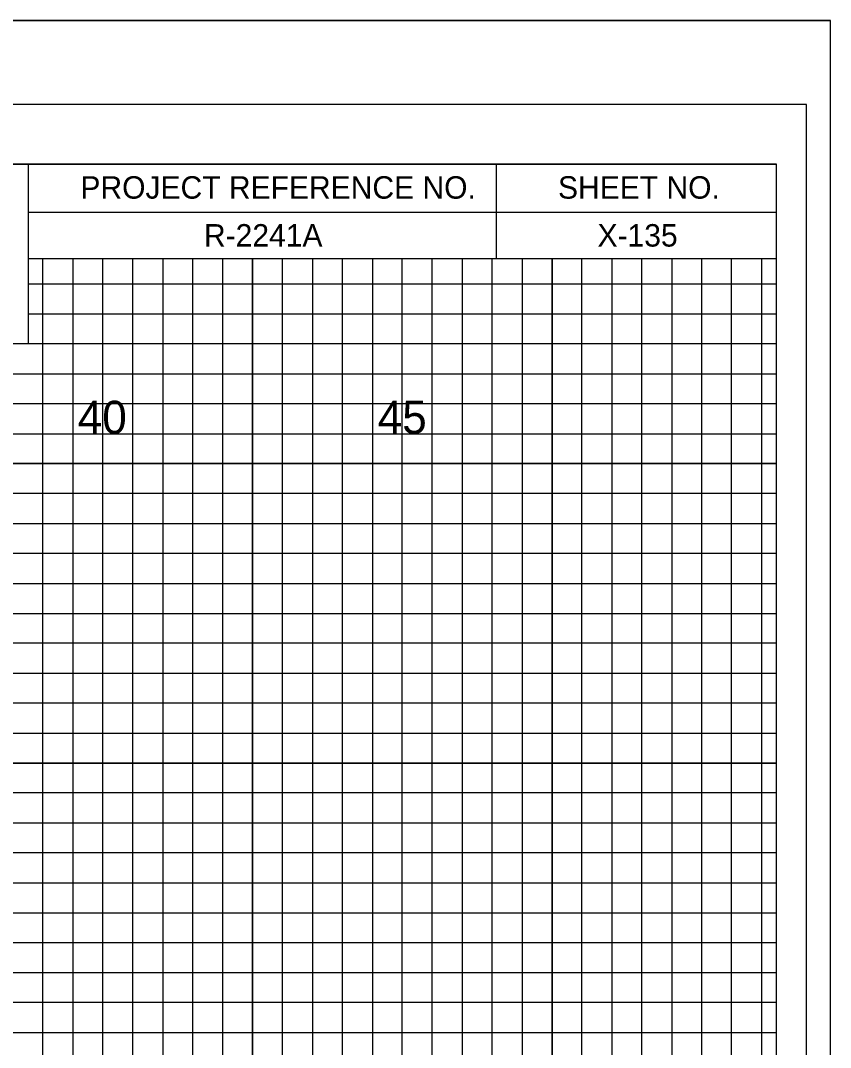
# Model space of a CAD drawing. Extents: x -4 to 103, y -2 to 280.
# Drawn here: x 89.87 to 103.4, y 262.73 to 279.88 of the extents above; entities that cross this region are included whole.
import ezdxf

# ---------------------------------------------------------------- set-up
doc = ezdxf.new("R2010")
doc.units = 0
for name, color, linetype in [('Exist XS Center Line Elevation Label', 7, 'Continuous'), ('Old_Level_63', 7, 'Continuous'), ('Prop XS Dump Level', 7, 'Continuous'), ('Prop XS Pvmt Edge Slope', 7, 'Continuous'), ('Prop XS SE Text', 7, 'Continuous'), ('Prop XS Side Slope Text', 7, 'Continuous'), ('Prop XS SS Elevation Text', 7, 'Continuous'), ('Sheet Cutting Line CELL', 7, 'Continuous'), ('Sheet Plot Border Inside CELL', 7, 'Continuous'), ('Sheet Plot Border Outside CELL', 7, 'Continuous')]:
    doc.layers.add(name, color=color, linetype=linetype)

msp = doc.modelspace()

# ---------------------------------------------------------------- linework, layer by layer
at = {"layer": 'Exist XS Center Line Elevation Label'}
for points in [[(91.25, 212.475), (91.25, 275.9), (93.75, 275.9), (93.75, 212.475)], [(96.25, 212.475), (96.25, 275.9), (98.75, 275.9), (98.75, 212.475)], [(101.25, 212.475), (101.25, 275.9)], [(90, 274.975), (102.5, 274.975)], [(0, 269.975), (102.5, 269.975), (102.5, 272.475), (0, 272.475)], [(0, 264.975), (102.5, 264.975), (102.5, 267.475), (0, 267.475)]]:
    msp.add_lwpolyline(points, dxfattribs=at)
at = {"layer": 'Old_Level_63'}
for p, q in [((90, 277.475), (102.5, 277.475)), ((90, 277.475), (102.5, 277.475)), ((97.825, 275.9), (97.825, 277.475)), ((101.875, 277.475), (101.875, 277.475)), ((102.5, 277.475), (102.5, 277.475)), ((102.5, 275.9), (102.5, 277.475)), ((102.5, 277.475), (102.5, 277.475)), ((102.5, 277.475), (102.5, 277.475)), ((102.5, 275.9), (102.5, 277.475)), ((90, 276.675), (102.5, 276.675)), ((90, 275.9), (102.5, 275.9)), ((99.4, 275.9), (99.4, 275.9)), ((99.4, 275.9), (99.4, 275.9))]:
    msp.add_line(p, q, dxfattribs=at)
for points in [[(102.5, 277.475), (0, 277.475), (0, 212.475), (102.5, 212.475)], [(83.75, 277.475), (90, 277.475), (90, 274.475), (83.75, 274.475)]]:
    msp.add_lwpolyline(points, close=True, dxfattribs=at)
at = {"layer": 'Prop XS Dump Level'}
for p, q in [((91.25, 212.475), (91.25, 275.9)), ((93.75, 212.475), (93.75, 275.9)), ((96.25, 212.475), (96.25, 275.9)), ((98.75, 212.475), (98.75, 275.9)), ((101.25, 212.475), (101.25, 275.9)), ((90, 274.975), (102.5, 274.975)), ((0, 272.475), (102.5, 272.475)), ((0, 269.975), (102.5, 269.975)), ((0, 267.475), (102.5, 267.475)), ((0, 264.975), (102.5, 264.975))]:
    msp.add_line(p, q, dxfattribs=at)
at = {"layer": 'Prop XS SE Text'}
for points in [[(90.25, 212.475), (90.25, 275.9), (90.75, 275.9), (90.75, 212.475)], [(91.75, 212.475), (91.75, 275.9), (92.25, 275.9), (92.25, 212.475)], [(92.75, 212.475), (92.75, 275.9), (93.25, 275.9), (93.25, 212.475)], [(94.25, 212.475), (94.25, 275.9), (94.75, 275.9), (94.75, 212.475)], [(95.25, 212.475), (95.25, 275.9), (95.75, 275.9), (95.75, 212.475)], [(96.75, 212.475), (96.75, 275.9), (97.25, 275.9), (97.25, 212.475)], [(97.75, 212.475), (97.75, 275.9), (98.25, 275.9), (98.25, 212.475)], [(99.25, 212.475), (99.25, 275.9), (99.75, 275.9), (99.75, 212.475)], [(100.25, 212.475), (100.25, 275.9)], [(100.25, 275.9), (100.75, 275.9), (100.75, 212.475), (101.75, 212.475), (101.75, 275.9), (102.25, 275.9), (102.25, 212.475)], [(102.5, 274.475), (102.5, 275.475), (90, 275.475)], [(0, 273.975), (102.5, 273.975), (102.5, 274.475), (0, 274.475)], [(0, 272.975), (102.5, 272.975), (102.5, 273.475), (0, 273.475)], [(0, 271.475), (102.5, 271.475), (102.5, 271.975), (0, 271.975)], [(0, 270.475), (102.5, 270.475), (102.5, 270.975), (0, 270.975)], [(0, 268.975), (102.5, 268.975), (102.5, 269.475), (0, 269.475)], [(0, 267.975), (102.5, 267.975), (102.5, 268.475), (0, 268.475)], [(0, 266.475), (102.5, 266.475), (102.5, 266.975), (0, 266.975)], [(0, 265.475), (102.5, 265.475), (102.5, 265.975), (0, 265.975)], [(0, 263.975), (102.5, 263.975), (102.5, 264.475), (0, 264.475)], [(0, 262.975), (102.5, 262.975), (102.5, 263.475), (0, 263.475)]]:
    msp.add_lwpolyline(points, dxfattribs=at)
at = {"layer": 'Sheet Cutting Line CELL'}
msp.add_line((-3.5, 279.875), (103.4, 279.875), dxfattribs=at)
at = {"layer": 'Sheet Plot Border Inside CELL'}
msp.add_lwpolyline([(103, 278.475), (-2.8, 278.475), (-2.8, 211.475), (103, 211.475)], close=True, dxfattribs=at)
at = {"layer": 'Sheet Plot Border Outside CELL'}
msp.add_lwpolyline([(103.4, 279.875), (-3.5, 279.875), (-3.5, 210.05), (103.4, 210.05)], close=True, dxfattribs=at)

# ---------------------------------------------------------------- texts
at = {"layer": 'Old_Level_63'}
for s, p in [('PROJECT REFERENCE NO.', (90.875, 276.9)), ('SHEET NO.', (98.85, 276.9))]:
    msp.add_text(s, height=0.375, dxfattribs=at).set_placement(p)
at = {"layer": 'Prop XS Pvmt Edge Slope'}
for s, p in [('40', (90.831, 272.975)), ('45', (95.84, 272.975))]:
    msp.add_text(s, height=0.55, dxfattribs=at).set_placement(p)
at = {"layer": 'Prop XS Side Slope Text'}
msp.add_text('X-135', height=0.375, dxfattribs=at).set_placement((99.51, 276.1))
at = {"layer": 'Prop XS SS Elevation Text'}
msp.add_text('R-2241A', height=0.375, dxfattribs=at).set_placement((92.938, 276.1))

doc.saveas('drawing.dxf')
